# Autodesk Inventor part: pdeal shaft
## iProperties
Author: Administrator
Created: 2001-03
Part Number: pdeal shaft
Document SubType Name: Modeling
Designer: Administrator
Control State: 0
Master: False
Checked Out: False
PropertySet Name: Design Tracking Control
Shininess: 20.0
PropertySet Name: _Private Model Information
Density: 0.0
Volumn: 0.0
Area: 0.0
PropertySet Name: Model Information
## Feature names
1. Extrusion1
2. Chamfer1
3. Revolution1
